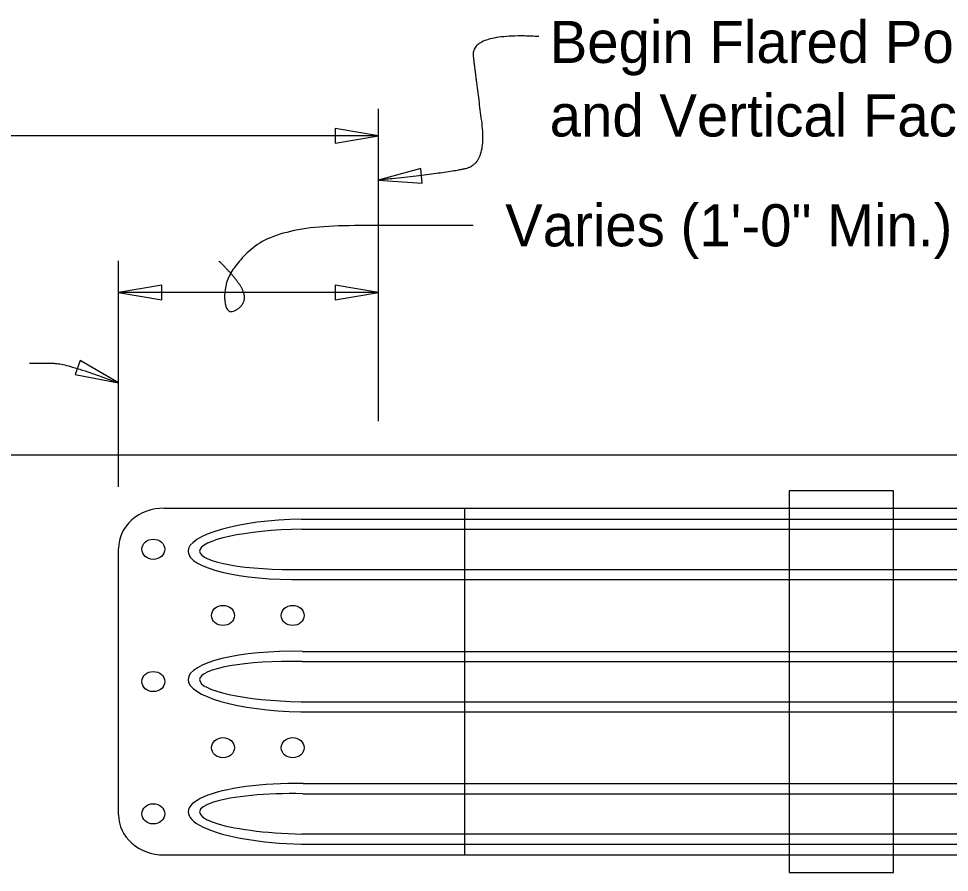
# Model space of a CAD drawing. Extents: x 2.6 to 35.7, y 1.7 to 23.4.
# Drawn here: x 9.781 to 14.234, y 8.75 to 12.837 of the extents above; entities that cross this region are included whole.
import ezdxf

# ---------------------------------------------------------------- set-up
doc = ezdxf.new("R2010")
doc.units = 0
for name, color, linetype in [('Dimension', 7, 'Continuous'), ('Miscellaneous', 7, 'Continuous'), ('SteelMisc_h', 7, 'Continuous'), ('TextStructures', 7, 'Continuous'), ('TrafBarrierConc', 7, 'Continuous')]:
    doc.layers.add(name, color=color, linetype=linetype)

msp = doc.modelspace()

# ---------------------------------------------------------------- linework, layer by layer
at = {"layer": 'Dimension'}
for p, q in [((11.5031, 10.9099), (11.5031, 12.4043)), ((10.2582, 10.5952), (10.2582, 11.6771)), ((11.5031, 11.5258), (10.2582, 11.5258))]:
    msp.add_line(p, q, dxfattribs=at)
msp.add_lwpolyline([(11.5009, 12.2758), (8.5242, 12.2758), (8.5242, 12.1596), (8.4248, 12.3846), (8.4248, 12.2758), (4.9253, 12.2758)], dxfattribs=at)
for points in [[(11.5031, 12.2758), (11.2949, 12.3111), (11.2949, 12.2405)], [(11.5009, 12.0637), (11.7116, 12.049), (11.7047, 12.1192)], [(10.2582, 11.5258), (10.4665, 11.4905), (10.4665, 11.5611)], [(11.5031, 11.5258), (11.2949, 11.5611), (11.2949, 11.4905)], [(10.2582, 11.0933), (10.0757, 11.1995), (10.0509, 11.1335)]]:
    msp.add_lwpolyline(points, close=True, dxfattribs=at)
for points in [[(12.2698, 12.7508), (11.9408, 12.7705), (11.9703, 12.5393), (12.0204, 12.1417), (11.8178, 12.0949), (11.5009, 12.0638)], [(11.9556, 11.8458), (11.7393, 11.8458), (11.0216, 11.8458), (10.766, 11.6195), (10.766, 11.4129), (10.8693, 11.4671), (10.8497, 11.5679), (10.7391, 11.6762)], [(9.8323, 11.1868), (9.8962, 11.1868), (10.0092, 11.1868), (10.2582, 11.0933)]]:
    msp.add_open_spline(points, degree=2, dxfattribs=at)
at = {"layer": 'Miscellaneous'}
for p, q in [((10.4769, 10.4934), (17.9962, 10.4934)), ((11.9161, 8.8332), (11.9161, 10.4934)), ((11.1345, 10.4413), (17.9962, 10.4413)), ((11.1357, 10.393), (17.9962, 10.393)), ((10.2582, 9.0261), (10.2582, 10.3006)), ((11.1404, 10.2002), (17.9962, 10.2002)), ((11.1416, 10.152), (17.9962, 10.152)), ((11.1381, 9.808), (17.9962, 9.808)), ((11.1369, 9.7598), (17.9962, 9.7598)), ((11.1321, 9.567), (17.9962, 9.567)), ((11.1309, 9.5189), (17.9962, 9.5189)), ((11.1416, 9.1749), (17.9962, 9.1749)), ((11.1404, 9.1267), (17.9962, 9.1267)), ((11.1357, 8.9339), (17.9962, 8.9339)), ((11.1345, 8.8856), (17.9962, 8.8856)), ((10.4769, 8.8333), (17.9962, 8.8333))]:
    msp.add_line(p, q, dxfattribs=at)
msp.add_lwpolyline([(13.4665, 8.75), (13.9665, 8.75), (13.9665, 10.5767), (13.4665, 10.5767)], close=True, dxfattribs=at)
for centre, major_axis, ratio, start_param, end_param in [((10.4769, 10.3007), (0.2185, 0), 0.882613, 1.570796, 3.141593), ((11.1381, 10.2966), (-0.5464, -0.0102), 0.264749, 4.713933, 7.855525), ((11.1381, 10.2966), (-0.4917, -0.0093), 0.196063, 4.713495, 7.855087), ((11.1345, 9.6634), (-0.5428, 0.0103), 0.266477, 4.71081, 7.852402), ((11.1345, 9.6634), (-0.4882, 0.0094), 0.197486, 4.711258, 7.85285), ((11.1381, 9.0302), (-0.5464, 0.0102), 0.264749, 4.710845, 7.852438), ((11.1381, 9.0302), (-0.4917, 0.0093), 0.196063, 4.711283, 7.852876), ((10.4769, 9.0262), (0.2185, 0), 0.882613, 3.141593, 4.712389)]:
    msp.add_ellipse(centre, major_axis=major_axis, ratio=ratio, start_param=start_param, end_param=end_param, dxfattribs=at)
at = {"layer": 'SteelMisc_h'}
for centre in [(10.425, 10.2966), (10.7584, 9.98), (11.0917, 9.98), (10.425, 9.6634), (10.7584, 9.3469), (11.0917, 9.3469), (10.425, 9.0302)]:
    msp.add_ellipse(centre, major_axis=(0.0547, 0), ratio=0.882613, dxfattribs=at)
at = {"layer": 'TrafBarrierConc'}
msp.add_line((17.4572, 10.7467), (8.4846, 10.7467), dxfattribs=at)

# ---------------------------------------------------------------- texts
at = {"layer": 'Dimension'}
for s, p in [('Begin Flared Portion of Wing Wall', (12.3215, 12.6244)), ('and Vertical Face Retrofit Railing', (12.3215, 12.2724))]:
    msp.add_text(s, height=0.2016, dxfattribs=at).set_placement(p)
at = {"layer": 'TextStructures'}
msp.add_text('Varies (1\'-0" Min.)', height=0.2016, dxfattribs=at).set_placement((12.1084, 11.7467))

doc.saveas('drawing.dxf')
